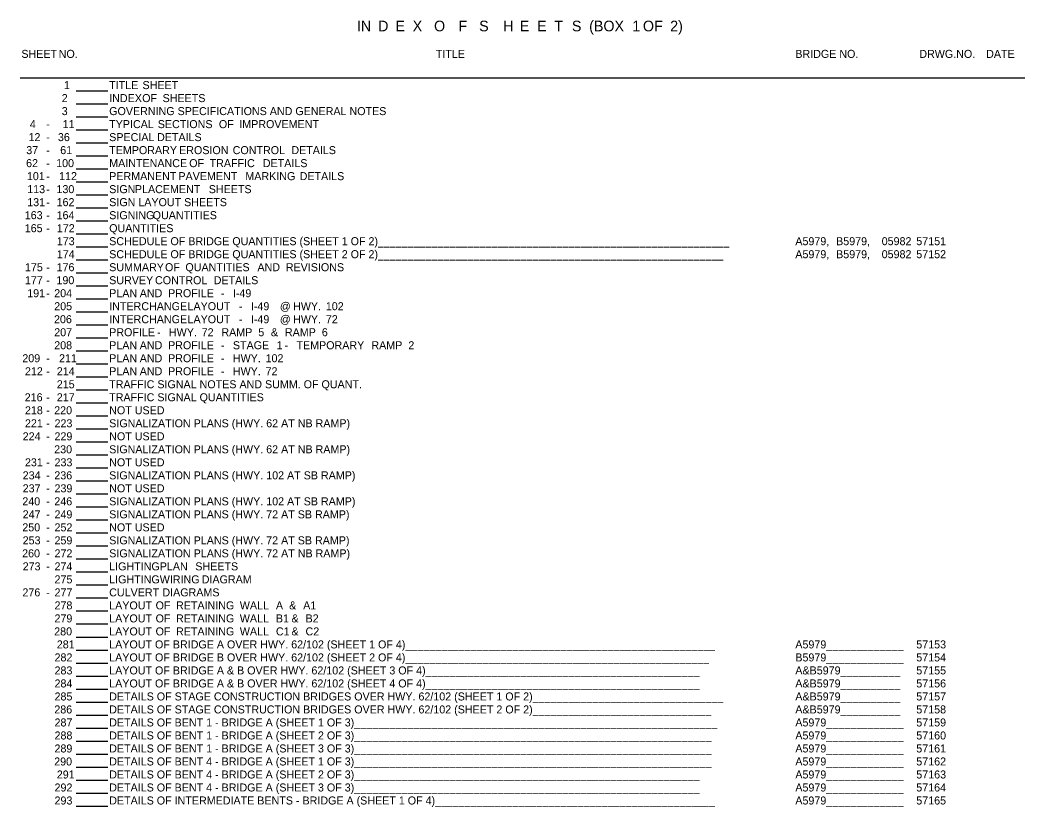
# Model space of a CAD drawing. Extents: x 1224738 to 1230974, y 151304 to 152345.
# Drawn here: x 1226603 to 1227249, y 151827 to 152332 of the extents above; entities that cross this region are included whole.
import ezdxf

# ---------------------------------------------------------------- set-up
doc = ezdxf.new("R2010")
doc.units = 0
doc.layers.add('R_Dimension', color=7, linetype='Continuous')

msp = doc.modelspace()

# ---------------------------------------------------------------- linework, layer by layer
at = {"layer": 'R_Dimension'}
for p, q in [((1226603.33, 152295.38), (1227249.09, 152295.38)), ((1226639.27, 152287.02), (1226659.75, 152287.02)), ((1226639.27, 152278.66), (1226659.75, 152278.66)), ((1226639.27, 152270.3), (1226659.75, 152270.3)), ((1226639.27, 152261.94), (1226659.75, 152261.94)), ((1226639.27, 152253.58), (1226659.75, 152253.58)), ((1226639.27, 152245.22), (1226659.75, 152245.22)), ((1226639.27, 152236.86), (1226659.75, 152236.86)), ((1226639.27, 152228.5), (1226659.75, 152228.5)), ((1226639.27, 152220.14), (1226659.75, 152220.14)), ((1226639.27, 152211.78), (1226659.75, 152211.78)), ((1226639.27, 152203.42), (1226659.75, 152203.42)), ((1226639.27, 152195.06), (1226659.75, 152195.06)), ((1226639.27, 152186.7), (1226659.75, 152186.7)), ((1226639.27, 152178.35), (1226659.75, 152178.35)), ((1226639.27, 152169.99), (1226659.75, 152169.99)), ((1226639.27, 152161.63), (1226659.75, 152161.63)), ((1226639.27, 152153.27), (1226659.75, 152153.27)), ((1226639.27, 152144.91), (1226659.75, 152144.91)), ((1226639.27, 152136.55), (1226659.75, 152136.55)), ((1226639.27, 152128.19), (1226659.75, 152128.19)), ((1226639.27, 152119.83), (1226659.75, 152119.83)), ((1226639.27, 152111.47), (1226659.75, 152111.47)), ((1226639.27, 152103.11), (1226659.75, 152103.11)), ((1226639.27, 152094.75), (1226659.75, 152094.75)), ((1226639.27, 152086.39), (1226659.75, 152086.39)), ((1226639.27, 152078.03), (1226659.75, 152078.03)), ((1226639.27, 152069.67), (1226659.75, 152069.67)), ((1226639.27, 152061.31), (1226659.75, 152061.31)), ((1226639.27, 152052.95), (1226659.75, 152052.95)), ((1226639.27, 152044.6), (1226659.75, 152044.6)), ((1226639.27, 152036.24), (1226659.75, 152036.24)), ((1226639.27, 152027.88), (1226659.75, 152027.88)), ((1226639.27, 152019.52), (1226659.75, 152019.52)), ((1226639.27, 152011.16), (1226659.75, 152011.16)), ((1226639.27, 152002.8), (1226659.75, 152002.8)), ((1226639.27, 151994.44), (1226659.75, 151994.44)), ((1226639.27, 151986.08), (1226659.75, 151986.08)), ((1226639.27, 151977.72), (1226659.75, 151977.72)), ((1226639.27, 151969.36), (1226659.75, 151969.36)), ((1226639.27, 151961), (1226659.75, 151961)), ((1226639.27, 151952.64), (1226659.75, 151952.64)), ((1226639.27, 151944.28), (1226659.75, 151944.28)), ((1226639.27, 151935.92), (1226659.75, 151935.92)), ((1226639.27, 151927.56), (1226659.75, 151927.56)), ((1226639.27, 151919.2), (1226659.75, 151919.2)), ((1226639.27, 151910.84), (1226659.75, 151910.84)), ((1226639.27, 151902.49), (1226659.75, 151902.49)), ((1226639.27, 151894.13), (1226659.75, 151894.13)), ((1226639.27, 151885.77), (1226659.75, 151885.77)), ((1226639.27, 151877.41), (1226659.75, 151877.41)), ((1226639.27, 151869.05), (1226659.75, 151869.05)), ((1226639.27, 151860.69), (1226659.75, 151860.69)), ((1226639.27, 151852.33), (1226659.75, 151852.33)), ((1226639.27, 151843.97), (1226659.75, 151843.97)), ((1226639.27, 151835.61), (1226659.75, 151835.61)), ((1226639.27, 151827.25), (1226659.75, 151827.25))]:
    msp.add_line(p, q, dxfattribs=at)

# ---------------------------------------------------------------- texts
for s, height, p in [('I', 6.86, (1226819.76, 152325.17)), (' N', 6.859, (1226819.76, 152325.17)), (' D', 6.859, (1226830.88, 152325.17)), (' E', 6.859, (1226842.01, 152325.17)), (' X', 6.859, (1226853.08, 152325.17)), ('  O', 6.859, (1226864.26, 152325.17)), (' F', 6.859, (1226882.46, 152325.17)), ('  S', 6.859, (1226893.26, 152325.17)), (' H', 6.859, (1226911.19, 152325.17)), (' E', 6.859, (1226921.94, 152325.17)), (' E', 6.859, (1226933.01, 152325.17)), (' T', 6.859, (1226944.09, 152325.17)), (' S', 6.859, (1226955.43, 152325.17)), (' (BOX', 6.859, (1226966.5, 152325.17)), (' 1', 6.859, (1226994.2, 152325.17)), (' OF', 6.859, (1227001.06, 152325.17)), (' 2)', 6.859, (1227018.56, 152325.17)), ('SHEET', 5.144, (1226604.16, 152308.11)), (' NO.', 5.144, (1226626.24, 152308.11)), ('TITLE', 5.144, (1226870.47, 152308.11)), ('BRIDGE NO.', 5.144, (1227101.55, 152308.11)), ('DRWG.NO.', 5.144, (1227181.24, 152308.11)), ('DATE', 5.144, (1227224.17, 152308.11)), ('1', 5.14, (1226631.54, 152288.05)), ('TITLE', 5.144, (1226660.59, 152288.05)), (' SHEET', 5.144, (1226680.11, 152288.05)), ('2', 5.14, (1226630.08, 152279.69)), ('INDEX', 5.144, (1226660.59, 152279.69)), (' OF', 5.144, (1226679.87, 152279.69)), (' SHEETS', 5.144, (1226692.99, 152279.69)), ('3', 5.14, (1226630.08, 152271.33)), ('GOVERNING SPECIFICATIONS AND GENERAL NOTES', 5.1443, (1226660.59, 152271.33)), ('4', 5.14, (1226609.6, 152262.97)), ('-', 5.14, (1226620.04, 152262.97)), ('11', 5.144, (1226630.69, 152262.97)), ('TYPICAL', 5.144, (1226660.59, 152262.97)), (' SECTIONS', 5.144, (1226689.91, 152262.97)), (' OF', 5.144, (1226729.16, 152262.97)), (' IMPROVEMENT', 5.1443, (1226742.29, 152262.97)), ('12', 5.144, (1226608.75, 152254.61)), ('36', 5.144, (1226627.63, 152254.61)), ('SPECIAL', 5.144, (1226660.59, 152254.61)), (' DETAILS', 5.144, (1226689.43, 152254.61)), ('-', 5.14, (1226620.04, 152254.61)), ('37', 5.144, (1226607.29, 152246.25)), ('-', 5.14, (1226620.04, 152246.25)), ('61', 5.144, (1226629.11, 152246.25)), ('TEMPORARY', 5.144, (1226660.59, 152246.25)), (' EROSION', 5.144, (1226703.61, 152246.25)), (' CONTROL', 5.144, (1226738.04, 152246.25)), (' DETAILS', 5.144, (1226775.75, 152246.25)), ('62', 5.144, (1226607.17, 152237.89)), ('-', 5.14, (1226620.04, 152237.89)), ('100', 5.144, (1226626.5, 152237.89)), ('MAINTENANCE', 5.1443, (1226660.59, 152237.89)), (' OF', 5.144, (1226710.09, 152237.89)), (' TRAFFIC', 5.144, (1226723.21, 152237.89)), (' DETAILS', 5.144, (1226757.4, 152237.89)), ('101', 5.144, (1226607.7, 152229.53)), ('112', 5.144, (1226628.38, 152229.53)), ('PERMANENT', 5.144, (1226660.59, 152229.53)), (' PAVEMENT', 5.144, (1226703.16, 152229.53)), (' MARKING', 5.144, (1226746.18, 152229.53)), (' DETAILS', 5.144, (1226781.09, 152229.53)), ('113', 5.144, (1226607.9, 152221.17)), ('-', 5.14, (1226620.04, 152229.53)), ('130', 5.144, (1226626.7, 152221.17)), ('SIGN', 5.144, (1226660.59, 152221.17)), (' PLACEMENT', 5.144, (1226675.21, 152221.17)), (' SHEETS', 5.144, (1226722.68, 152221.17)), ('-', 5.14, (1226620.04, 152221.17)), ('131', 5.144, (1226607.9, 152212.81)), ('-', 5.14, (1226620.04, 152212.81)), ('162', 5.144, (1226626.8, 152212.81)), ('SIGN LAYOUT SHEETS', 5.1443, (1226660.59, 152212.81)), ('163', 5.144, (1226606.32, 152204.45)), ('-', 5.14, (1226620.04, 152204.45)), ('164', 5.144, (1226626.8, 152204.45)), ('SIGNING', 5.144, (1226660.59, 152204.45)), (' QUANTITIES', 5.1443, (1226686.63, 152204.45)), ('165', 5.144, (1226606.32, 152196.09)), ('172', 5.144, (1226626.92, 152196.09)), ('QUANTITIES', 5.144, (1226660.59, 152196.09)), ('-', 5.14, (1226620.04, 152196.09)), ('173', 5.144, (1226626.92, 152187.73)), ('SCHEDULE OF BRIDGE QUANTITIES (SHEET 1 OF 2)___________________________________________________________', 5.14425, (1226660.59, 152187.73)), ('A5979,', 5.144, (1227101.55, 152187.73)), (' B5979,', 5.144, (1227125.85, 152187.73)), (' 05982', 5.144, (1227155.14, 152187.73)), ('57151', 5.144, (1227179.29, 152187.73)), ('174', 5.144, (1226626.92, 152179.37)), ('SCHEDULE OF BRIDGE QUANTITIES (SHEET 2 OF 2)__________________________________________________________', 5.14425, (1226660.59, 152179.37)), ('A5979,', 5.144, (1227101.55, 152179.37)), (' B5979,', 5.144, (1227125.85, 152179.37)), (' 05982', 5.144, (1227155.14, 152179.37)), ('57152', 5.144, (1227179.29, 152179.37)), ('175', 5.144, (1226606.44, 152171.01)), ('176', 5.144, (1226626.78, 152171.01)), ('SUMMARY', 5.144, (1226660.59, 152171.01)), (' OF', 5.144, (1226694.53, 152171.01)), (' QUANTITIES', 5.1443, (1226707.66, 152171.01)), (' AND', 5.144, (1226753.95, 152171.01)), (' REVISIONS', 5.144, (1226772.18, 152171.01)), ('-', 5.14, (1226620.04, 152171.01)), ('190', 5.144, (1226626.7, 152162.66)), ('SURVEY', 5.144, (1226660.59, 152162.66)), (' CONTROL', 5.144, (1226688.13, 152162.66)), (' DETAILS', 5.144, (1226725.84, 152162.66)), ('177', 5.144, (1226606.44, 152162.66)), ('-', 5.14, (1226620.04, 152162.66)), ('191', 5.144, (1226607.9, 152154.3)), ('-', 5.14, (1226620.04, 152154.3)), ('204', 5.144, (1226625.26, 152154.3)), ('PLAN', 5.144, (1226660.59, 152154.3)), (' AND', 5.144, (1226678.29, 152154.3)), (' PROFILE', 5.144, (1226696.52, 152154.3)), (' -', 5.144, (1226730.5, 152154.3)), (' I-49', 5.144, (1226738.16, 152154.3)), ('205', 5.144, (1226625.26, 152145.94)), ('INTERCHANGE', 5.1443, (1226660.59, 152145.94)), (' LAYOUT', 5.144, (1226709.03, 152145.94)), (' I-49', 5.144, (1226749.74, 152145.94)), (' @', 5.144, (1226768.37, 152145.94)), (' HWY.', 5.144, (1226776.88, 152145.94)), (' 102', 5.144, (1226797.9, 152145.94)), ('206', 5.144, (1226625.12, 152137.58)), ('INTERCHANGE', 5.1443, (1226660.59, 152137.58)), (' LAYOUT', 5.144, (1226709.03, 152137.58)), (' -', 5.144, (1226742.09, 152145.94)), (' I-49', 5.144, (1226749.74, 152137.58)), (' @', 5.144, (1226768.37, 152137.58)), (' HWY.', 5.144, (1226776.88, 152137.58)), (' 72', 5.144, (1226797.9, 152137.58)), (' -', 5.144, (1226742.09, 152137.58)), ('207', 5.144, (1226625.26, 152129.22)), ('PROFILE', 5.144, (1226660.59, 152129.22)), (' -', 5.144, (1226689.43, 152129.22)), (' HWY.', 5.144, (1226697.08, 152129.22)), (' 72', 5.144, (1226718.11, 152129.22)), (' RAMP', 5.144, (1226730.79, 152129.22)), (' 5', 5.144, (1226754.52, 152129.22)), (' &', 5.144, (1226762.58, 152129.22)), (' RAMP', 5.144, (1226771.61, 152129.22)), (' 6', 5.144, (1226795.35, 152129.22)), ('208', 5.144, (1226625.26, 152120.86)), ('PLAN', 5.144, (1226660.59, 152120.86)), (' AND', 5.144, (1226678.29, 152120.86)), (' PROFILE', 5.144, (1226696.52, 152120.86)), (' -', 5.144, (1226730.5, 152120.86)), (' STAGE', 5.144, (1226738.16, 152120.86)), (' 1', 5.144, (1226766.23, 152120.86)), (' -', 5.144, (1226771.37, 152120.86)), (' TEMPORARY', 5.144, (1226779.03, 152120.86)), (' RAMP', 5.144, (1226827.19, 152120.86)), (' 2', 5.144, (1226850.93, 152120.86)), ('209', 5.144, (1226604.76, 152112.5)), ('211', 5.144, (1226628.38, 152112.5)), ('PLAN', 5.144, (1226660.59, 152112.5)), (' AND', 5.144, (1226678.29, 152112.5)), (' PROFILE', 5.144, (1226696.52, 152112.5)), (' HWY.', 5.144, (1226738.16, 152112.5)), (' 102', 5.144, (1226759.18, 152112.5)), ('-', 5.14, (1226620.04, 152112.5)), (' -', 5.144, (1226730.5, 152112.5)), ('212', 5.144, (1226606.44, 152104.14)), ('-', 5.14, (1226620.04, 152104.14)), ('214', 5.144, (1226626.92, 152104.14)), ('PLAN', 5.144, (1226660.59, 152104.14)), (' AND', 5.144, (1226678.29, 152104.14)), (' PROFILE', 5.144, (1226696.52, 152104.14)), (' -', 5.144, (1226730.5, 152104.14)), (' HWY.', 5.144, (1226738.16, 152104.14)), (' 72', 5.144, (1226759.18, 152104.14)), ('215', 5.144, (1226626.92, 152095.78)), ('TRAFFIC SIGNAL NOTES AND SUMM. OF QUANT.', 5.1443, (1226660.59, 152095.78)), ('216', 5.144, (1226606.3, 152087.42)), ('217', 5.144, (1226626.92, 152087.42)), ('TRAFFIC SIGNAL QUANTITIES', 5.1443, (1226660.59, 152087.42)), ('218', 5.144, (1226606.44, 152079.06)), ('-', 5.14, (1226620.04, 152087.42)), ('220', 5.144, (1226625.24, 152079.06)), ('NOT USED', 5.144, (1226660.59, 152079.06)), ('-', 5.14, (1226620.04, 152079.06)), ('221', 5.144, (1226606.44, 152070.7)), ('-', 5.14, (1226620.04, 152070.7)), ('223', 5.144, (1226625.46, 152070.7)), ('SIGNALIZATION PLANS (HWY. 62 AT NB RAMP)', 5.1443, (1226660.59, 152070.7)), ('224', 5.144, (1226604.98, 152062.34)), ('-', 5.14, (1226620.04, 152062.34)), ('229', 5.144, (1226625.44, 152062.34)), ('NOT USED', 5.144, (1226660.59, 152062.34)), ('230', 5.144, (1226625.24, 152053.98)), ('SIGNALIZATION PLANS (HWY. 62 AT NB RAMP)', 5.1443, (1226660.59, 152053.98)), ('231', 5.144, (1226606.44, 152045.62)), ('-', 5.14, (1226620.04, 152045.62)), ('233', 5.144, (1226625.46, 152045.62)), ('NOT USED', 5.144, (1226660.59, 152045.62)), ('234', 5.144, (1226604.98, 152037.26)), ('-', 5.14, (1226620.04, 152037.26)), ('236', 5.144, (1226625.32, 152037.26)), ('SIGNALIZATION PLANS (HWY. 102 AT SB RAMP)', 5.1443, (1226660.59, 152037.26)), ('237', 5.144, (1226604.98, 152028.91)), ('239', 5.144, (1226625.44, 152028.91)), ('NOT USED', 5.144, (1226660.59, 152028.91)), ('-', 5.14, (1226620.04, 152028.91)), ('SIGNALIZATION PLANS (HWY. 102 AT SB RAMP)', 5.1443, (1226660.59, 152020.55)), ('240', 5.144, (1226604.76, 152020.55)), ('-', 5.14, (1226620.04, 152020.55)), ('246', 5.144, (1226625.32, 152020.55)), ('247', 5.144, (1226604.98, 152012.19)), ('-', 5.14, (1226620.04, 152012.19)), ('249', 5.144, (1226625.44, 152012.19)), ('SIGNALIZATION PLANS (HWY. 72 AT SB RAMP)', 5.1443, (1226660.59, 152012.19)), ('250', 5.144, (1226604.76, 152003.83)), ('252', 5.144, (1226625.46, 152003.83)), ('NOT USED', 5.144, (1226660.59, 152003.83)), ('253', 5.144, (1226604.98, 151995.47)), ('-', 5.14, (1226620.04, 152003.83)), ('259', 5.144, (1226625.44, 151995.47)), ('SIGNALIZATION PLANS (HWY. 72 AT SB RAMP)', 5.1443, (1226660.59, 151995.47)), ('-', 5.14, (1226620.04, 151995.47)), ('260', 5.144, (1226604.64, 151987.11)), ('-', 5.14, (1226620.04, 151987.11)), ('272', 5.144, (1226625.46, 151987.11)), ('SIGNALIZATION PLANS (HWY. 72 AT NB RAMP)', 5.1443, (1226660.59, 151987.11)), ('273', 5.144, (1226604.98, 151978.75)), ('-', 5.14, (1226620.04, 151978.75)), ('274', 5.144, (1226625.46, 151978.75)), ('LIGHTING', 5.144, (1226660.59, 151978.75)), (' PLAN', 5.144, (1226691.17, 151978.75)), (' SHEETS', 5.144, (1226714.02, 151978.75)), ('275', 5.144, (1226625.46, 151970.39)), ('LIGHTING', 5.144, (1226660.59, 151970.39)), (' WIRING', 5.144, (1226691.17, 151970.39)), (' DIAGRAM', 5.144, (1226718.15, 151970.39)), ('276', 5.144, (1226604.84, 151962.03)), ('-', 5.14, (1226620.04, 151962.03)), ('277', 5.144, (1226625.46, 151962.03)), ('CULVERT', 5.144, (1226660.59, 151962.03)), (' DIAGRAMS', 5.144, (1226692.87, 151962.03)), ('278', 5.144, (1226625.46, 151953.67)), ('LAYOUT', 5.144, (1226660.59, 151953.67)), (' OF', 5.144, (1226688.5, 151953.67)), (' RETAINING', 5.144, (1226701.62, 151953.67)), (' WALL', 5.144, (1226742.61, 151953.67)), (' A', 5.144, (1226765.82, 151953.67)), (' &', 5.144, (1226774.33, 151953.67)), (' A1', 5.144, (1226783.36, 151953.67)), ('279', 5.144, (1226625.44, 151945.31)), ('LAYOUT', 5.144, (1226660.59, 151945.31)), (' OF', 5.144, (1226688.5, 151945.31)), (' RETAINING', 5.144, (1226701.62, 151945.31)), (' WALL', 5.144, (1226742.61, 151945.31)), (' B1', 5.144, (1226765.82, 151945.31)), (' &', 5.144, (1226775.83, 151945.31)), (' B2', 5.144, (1226784.86, 151945.31)), ('280', 5.144, (1226625.24, 151936.95)), ('LAYOUT', 5.144, (1226660.59, 151936.95)), (' OF', 5.144, (1226688.5, 151936.95)), (' RETAINING', 5.144, (1226701.62, 151936.95)), (' WALL', 5.144, (1226742.61, 151936.95)), (' C1', 5.144, (1226765.82, 151936.95)), (' &', 5.144, (1226775.83, 151936.95)), (' C2', 5.144, (1226784.86, 151936.95)), ('281', 5.144, (1226626.92, 151928.59)), ('LAYOUT OF BRIDGE A OVER HWY. 62/102 (SHEET 1 OF 4)____________________________________________________', 5.14425, (1226660.59, 151928.59)), ('A5979_____________', 5.1443, (1227101.55, 151928.59)), ('57153', 5.144, (1227179.29, 151928.59)), ('282', 5.144, (1226625.46, 151920.23)), ('LAYOUT OF BRIDGE B OVER HWY. 62/102 (SHEET 2 OF 4)___________________________________________________', 5.14425, (1226660.59, 151920.23)), ('B5979_____________', 5.1443, (1227101.55, 151920.23)), ('57154', 5.144, (1227179.29, 151920.23)), ('283', 5.144, (1226625.46, 151911.87)), ('LAYOUT OF BRIDGE A & B OVER HWY. 62/102 (SHEET 3 OF 4)______________________________________________', 5.1443, (1226660.59, 151911.87)), ('A&B5979__________', 5.1443, (1227101.55, 151911.87)), ('57155', 5.144, (1227179.29, 151911.87)), ('284', 5.144, (1226625.46, 151903.51)), ('LAYOUT OF BRIDGE A & B OVER HWY. 62/102 (SHEET 4 OF 4)______________________________________________', 5.1443, (1226660.59, 151903.51)), ('A&B5979__________', 5.1443, (1227101.55, 151903.51)), ('57156', 5.144, (1227179.29, 151903.51)), ('285', 5.144, (1226625.46, 151895.15)), ('DETAILS OF STAGE CONSTRUCTION BRIDGES OVER HWY. 62/102 (SHEET 1 OF 2)________________________________', 5.14425, (1226660.59, 151895.15)), ('A&B5979__________', 5.1443, (1227101.55, 151895.15)), ('57157', 5.144, (1227179.29, 151895.15)), ('286', 5.144, (1226625.32, 151886.8)), ('DETAILS OF STAGE CONSTRUCTION BRIDGES OVER HWY. 62/102 (SHEET 2 OF 2)______________________________', 5.1443, (1226660.59, 151886.8)), ('A&B5979__________', 5.1443, (1227101.55, 151886.8)), ('57158', 5.144, (1227179.29, 151886.8)), ('DETAILS OF BENT 1 - BRIDGE A (SHEET 1 OF 3)_____________________________________________________________', 5.14425, (1226660.59, 151878.44)), ('287', 5.144, (1226625.46, 151878.44)), ('A5979_____________', 5.1443, (1227101.55, 151878.44)), ('57159', 5.144, (1227179.29, 151878.44)), ('288', 5.144, (1226625.46, 151870.08)), ('DETAILS OF BENT 1 - BRIDGE A (SHEET 2 OF 3)____________________________________________________________', 5.14425, (1226660.59, 151870.08)), ('A5979_____________', 5.1443, (1227101.55, 151870.08)), ('57160', 5.144, (1227179.29, 151870.08)), ('289', 5.144, (1226625.44, 151861.72)), ('DETAILS OF BENT 1 - BRIDGE A (SHEET 3 OF 3)____________________________________________________________', 5.14425, (1226660.59, 151861.72)), ('A5979_____________', 5.1443, (1227101.55, 151861.72)), ('57161', 5.144, (1227179.29, 151861.72)), ('290', 5.144, (1226625.24, 151853.36)), ('DETAILS OF BENT 4 - BRIDGE A (SHEET 1 OF 3)____________________________________________________________', 5.14425, (1226660.59, 151853.36)), ('A5979_____________', 5.1443, (1227101.55, 151853.36)), ('57162', 5.144, (1227179.29, 151853.36)), ('291', 5.144, (1226626.92, 151845)), ('DETAILS OF BENT 4 - BRIDGE A (SHEET 2 OF 3)__________________________________________________________', 5.14425, (1226660.59, 151845)), ('A5979_____________', 5.1443, (1227101.55, 151845)), ('57163', 5.144, (1227179.29, 151845)), ('292', 5.144, (1226625.46, 151836.64)), ('DETAILS OF BENT 4 - BRIDGE A (SHEET 3 OF 3)__________________________________________________________', 5.14425, (1226660.59, 151836.64)), ('A5979_____________', 5.1443, (1227101.55, 151836.64)), ('57164', 5.144, (1227179.29, 151836.64)), ('293', 5.144, (1226625.46, 151828.28)), ('DETAILS OF INTERMEDIATE BENTS - BRIDGE A (SHEET 1 OF 4)_______________________________________________', 5.14425, (1226660.59, 151828.28)), ('A5979_____________', 5.1443, (1227101.55, 151828.28)), ('57165', 5.144, (1227179.29, 151828.28))]:
    msp.add_text(s, height=height, dxfattribs=at).set_placement(p)

doc.saveas('drawing.dxf')
